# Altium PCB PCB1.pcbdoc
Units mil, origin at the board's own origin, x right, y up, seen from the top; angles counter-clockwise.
Board outline 1771.65 x 787.4 mil, 2 copper layers (Top Layer, Bottom Layer); 6 components, 5 nets, 13 pads, 0 vias.
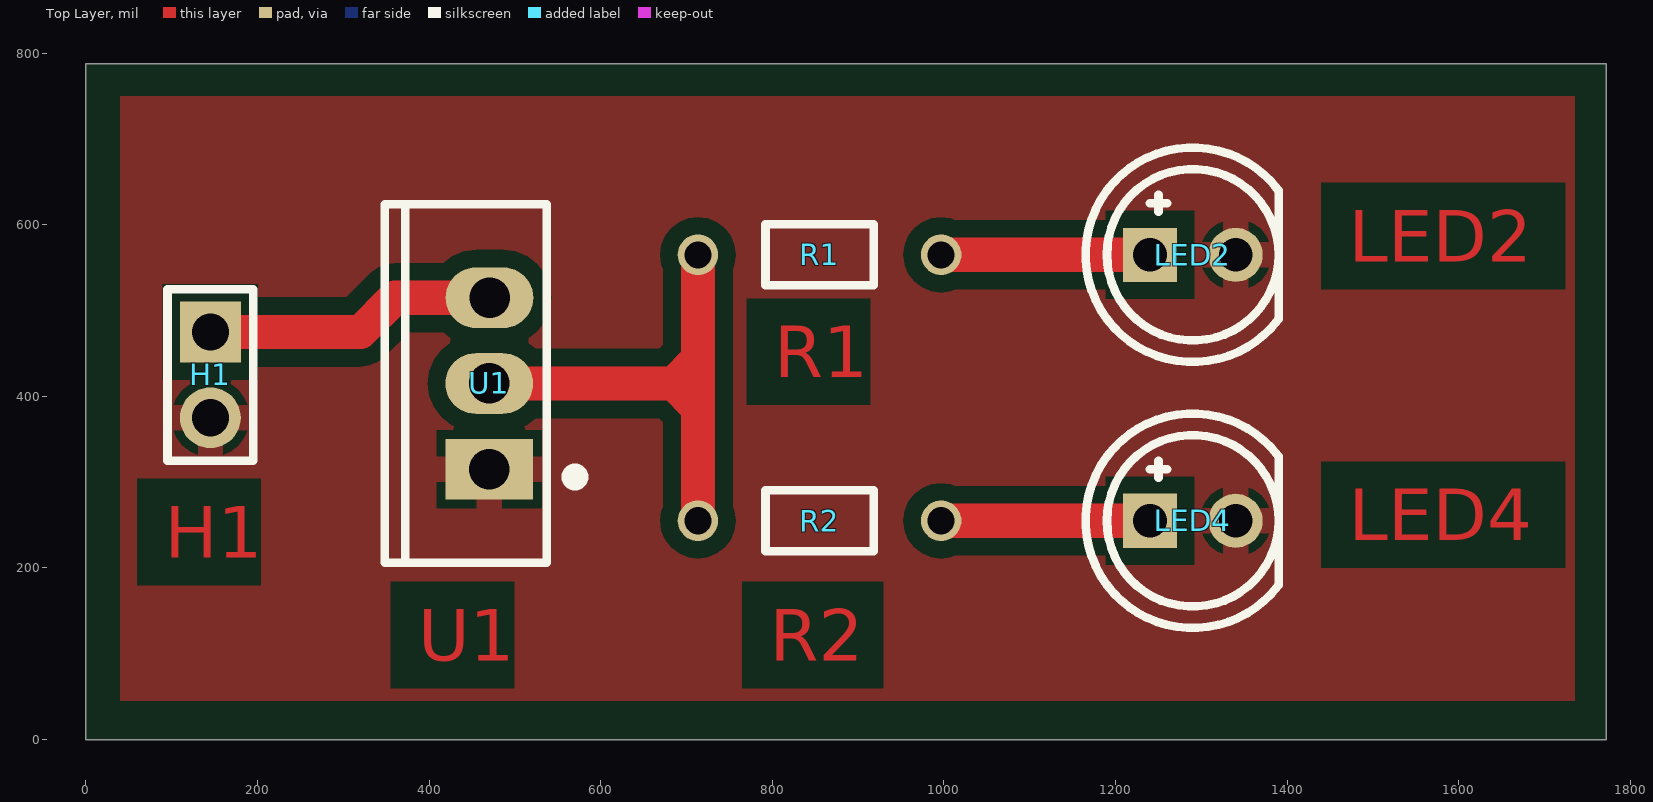
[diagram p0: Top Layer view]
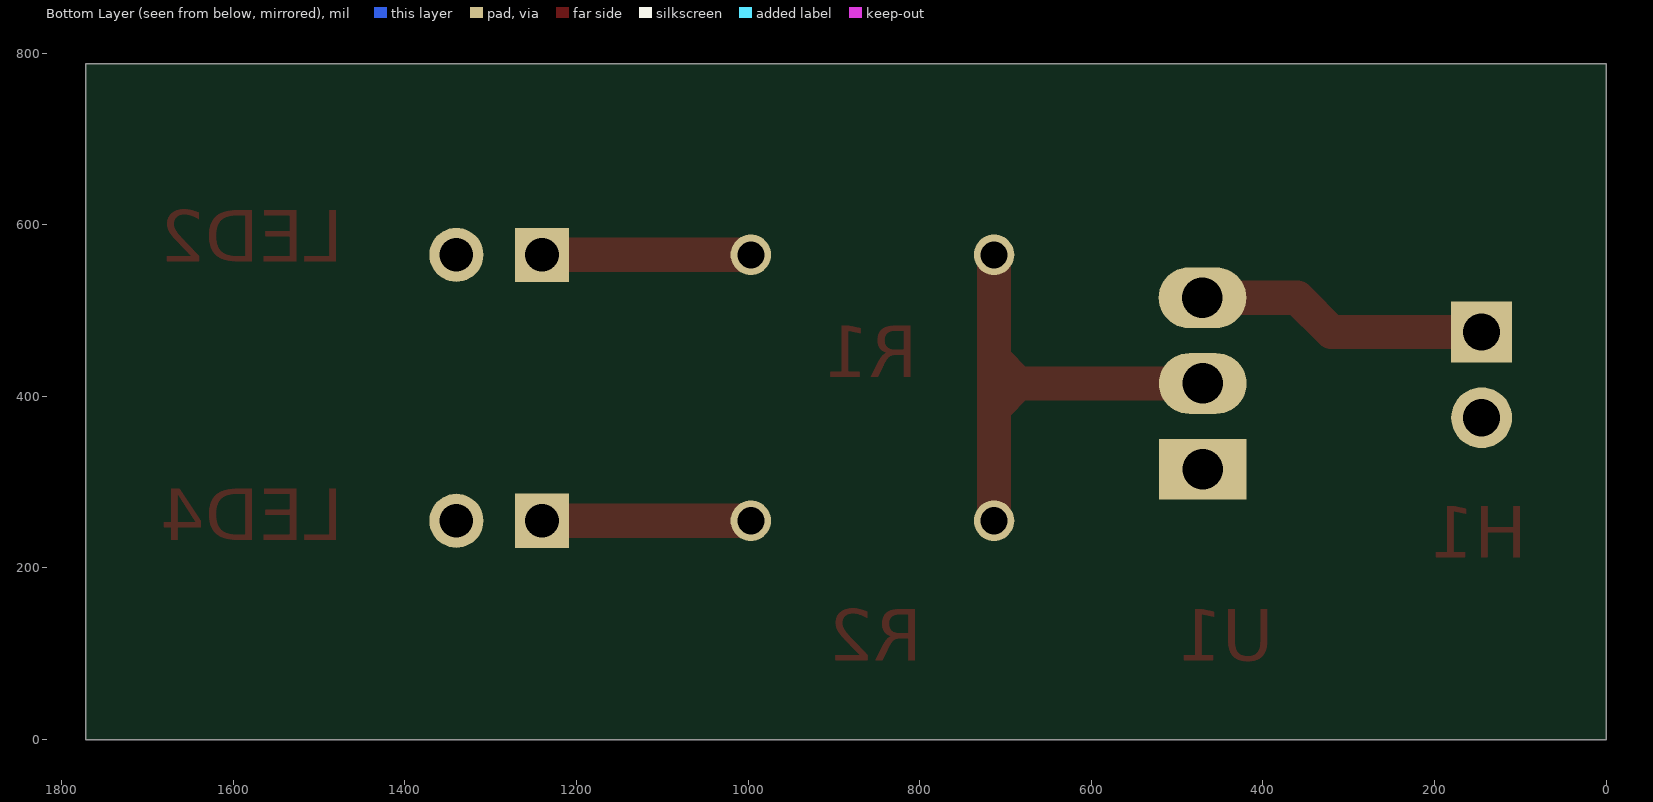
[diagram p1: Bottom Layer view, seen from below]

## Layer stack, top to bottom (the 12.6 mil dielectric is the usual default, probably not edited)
Top Solder Mask Layer: solder mask 0.4, Solder Resist, Dk 3.5
Top Layer: signal copper 1.4
Dielectric1: dielectric 12.6, FR-4, Dk 4.8
Bottom Layer: signal copper 1.4
Bottom Solder Mask Layer: solder mask 0.4, Solder Resist, Dk 3.5

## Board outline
0,0 0,787.4 1771.65,787.4 1771.65,0

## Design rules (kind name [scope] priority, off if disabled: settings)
BoardOutlineClearance copperThickness1oz_1 [All] p1: gap=10 ignorepadtopadclearanceinfootprint=FALSE except(0: Arc-SplitContinuation Track-SplitContinuation SMDPad-SplitContinuation THPad-SplitContinuation Via-SplitContinuation Fill-SplitContinuation Poly-SplitContinuation Region-SplitContinuation Text-SplitContinuation; 6: Track-CutoutEdge SMDPad-CutoutEdge THPad-CutoutEdge Via-CutoutEdge Region-CutoutEdge; 11.8: Track-OutlineEdge SMDPad-OutlineEdge THPad-OutlineEdge Via-OutlineEdge Fill-OutlineEdge Fill-CutoutEdge Poly-OutlineEdge Region-OutlineEdge Text-OutlineEdge)
BoardOutlineClearance copperThickness2oz_1 [All] p2: gap=10 ignorepadtopadclearanceinfootprint=FALSE except(0: Arc-SplitContinuation Track-SplitContinuation SMDPad-SplitContinuation THPad-SplitContinuation Via-SplitContinuation Fill-SplitContinuation Poly-SplitContinuation Region-SplitContinuation Text-SplitContinuation; 6: Track-CutoutEdge SMDPad-CutoutEdge THPad-CutoutEdge Via-CutoutEdge Region-CutoutEdge; 11.8: Track-OutlineEdge SMDPad-OutlineEdge THPad-OutlineEdge Via-OutlineEdge Fill-OutlineEdge Fill-CutoutEdge Poly-OutlineEdge Region-OutlineEdge Text-OutlineEdge)
Clearance copperThickness1oz [(InNet('GND') OR InNet('$1N430') OR InNet('$1N480') OR InNet('$1N588') OR InNet('$1N542') OR InNet('$1N614') OR InNet('$1N470'))] p1: gap=20 ignorepadtopadclearanceinfootprint=FALSE
Clearance copperThickness2oz [All] p2: gap=6 ignorepadtopadclearanceinfootprint=FALSE except(6.9: Track-Hole SMDPad-Hole THPad-Hole Via-Hole Fill-Hole Poly-Hole Region-Hole Text-Hole; 7: Arc-Arc Arc-Track Arc-SMDPad Arc-THPad Arc-Via Arc-Fill Arc-Poly Arc-Region Arc-Text Arc-Hole; 8: Track-Track; 11.8: Track-Fill Fill-Region)
DiffPairsRouting differentialPair [All] p1: maxlimit=6 minlimit=6 mostfreqgap=6 toplayer_minwidth=5 toplayer_maxwidth=100 toplayer_prefwidth=10 bottomlayer_minwidth=5 bottomlayer_maxwidth=100 bottomlayer_prefwidth=10 maxuncoupledlength=10
PasteMaskExpansion pasteMaskExpansion [All] p1: expansion=0
PlaneConnect innerPlane [All] p1: planeconnectstyle=Relief reliefexpansion=20 reliefentries=4 reliefconductorwidth=10 reliefairgap=10
PolygonConnect copperRegion [All] p1: thpad.connectstyle=Relief thpad.reliefconductorwidth=30 thpad.reliefentries=4 thpad.polygonreliefangle="90 Angle" thpad.airgapwidth=10 smdpad.connectstyle=Relief smdpad.reliefconductorwidth=10 smdpad.reliefentries=4 smdpad.polygonreliefangle="90 Angle" smdpad.airgapwidth=10 via.connectstyle=Relief via.reliefconductorwidth=10 via.reliefentries=4 via.polygonreliefangle="90 Angle" via.airgapwidth=10
RoutingVias viaSize [All] p1: holewidth=12.01 width=24.02 viastyle="Through Hole" minholewidth=11.81 minwidth=19.68 maxholewidth=248.03 maxwidth=393.7
SolderMaskExpansion solderMaskExpansion [All] p1: expansion=2 istentingtop=FALSE useseparateexpansions=TRUE expansionbottom=2 istentingbottom=FALSE
SupplyNets "Schematic Supply Nets" [InNet('GND')] p1: voltage=0.000
Width copperThickness1oz_2 [All] p1: maxlimit=100 minlimit=5 preferedwidth=10
Width copperThickness2oz_2 [All] p2: maxlimit=100 minlimit=8 preferedwidth=10
27 further rules are at their usual default settings.

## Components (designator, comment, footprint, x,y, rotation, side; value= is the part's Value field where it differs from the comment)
H1 "" HDR-TH_2P-P2.54-V-M-1 145,425 r270 top
LED2 "" LED-TH_BD5.8-P2.54-FD 1290,565 r0 top
LED4 "" LED-TH_BD5.8-P2.54-FD 1290,255 r0 top
R1 "10kΩ" RES-TH_BD1.8-L3.2-P7.20-D0.4 855,565 r180 top
R2 "10kΩ" RES-TH_BD1.8-L3.2-P7.20-D0.4 855,255 r180 top
U1 "LM1117T-3.3" TO-220-3_L10.0-W4.5-P2.54-L 470.2,415.01 r90 top

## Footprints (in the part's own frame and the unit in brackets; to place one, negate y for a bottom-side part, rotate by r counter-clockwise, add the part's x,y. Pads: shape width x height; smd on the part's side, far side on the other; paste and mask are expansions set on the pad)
HDR-TH_2P-P2.54-V-M-1 [mm]
  rect 1.8x1.8 hole 1.1: 1(-1.27,0)
  round 1.8 hole 1.1: 2(1.27,0)
  silkscreen extent -2.54,-1.27 2.54,1.27
LED-TH_BD5.8-P2.54-FD [mm]
  rect 1.6x1.6 hole 1: 1(-1.27,0)
  round 1.6 hole 1: 2(1.27,0)
  silkscreen extent -3.17,-3.17 2.54,3.17
RES-TH_BD1.8-L3.2-P7.20-D0.4 [mm]
  round 1.2 hole 0.8: 1(-3.6,0) 2(3.6,0)
  silkscreen extent -1.6,-0.9 1.6,0.9
TO-220-3_L10.0-W4.5-P2.54-L [mm]
  rect 1.8x2.6 hole 1.2: 1(-2.54,0.005)
  oval 1.8x2.6 hole 1.2: 2(0,0.005)
  oval 1.8x2.6 hole 1.2 copper offset 0,0: 3(2.54,-0.005)
  silkscreen extent -5.3,-2.73 5.3,3.09

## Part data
H1: library part HDR-M_2.54_1x2P
LED2 LED4: library part LED_TH-R_5mm
R1 R2: library part Res_AXIAL-1/8W

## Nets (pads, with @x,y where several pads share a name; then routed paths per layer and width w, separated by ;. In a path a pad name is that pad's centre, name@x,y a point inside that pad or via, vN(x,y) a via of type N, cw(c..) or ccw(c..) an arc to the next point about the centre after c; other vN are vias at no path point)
GND: H1.2 LED2.2 LED4.2 U1.1
NetH1_1: H1.1 U1.3 | length 342
  Top Layer w40: H1.1 320,475 360,515 U1.3
NetLED2_1: LED2.1 R1.1 | length 243.3
  Top Layer w40: R1.1 LED2.1
NetLED4_1: LED4.1 R2.1 | length 243.3
  Top Layer w40: R2.1 LED4.1
NetR1_2: R1.2 R2.2 U1.2 | length 605
  Top Layer w40: U1.2 685,415 ; R2.2 713.27,386.73 ; R1.2 713.27,443.27 ; 685,415 713.27,443.27 ; 685,415 713.27,386.73 ; 713.27,386.73 713.27,443.27

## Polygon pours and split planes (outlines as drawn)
GND on Top Layer "GND_L01_P000" (solid, remove dead copper, pour order 0): 40,45 1735,45 1735,750 40,750

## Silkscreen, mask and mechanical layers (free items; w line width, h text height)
Mechanical 1:
  the board outline again, w10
